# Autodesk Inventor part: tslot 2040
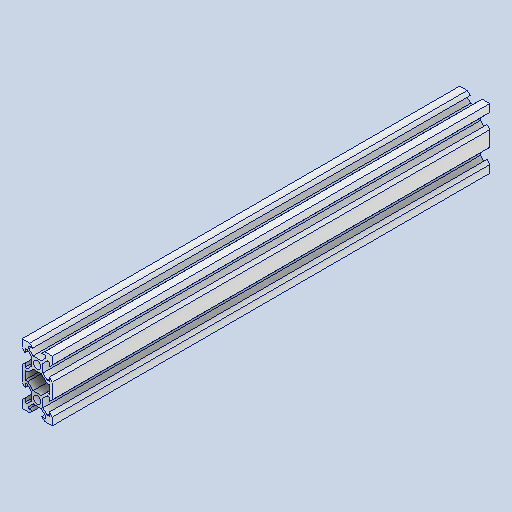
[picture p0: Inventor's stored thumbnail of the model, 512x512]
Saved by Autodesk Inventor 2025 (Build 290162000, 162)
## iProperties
Created: 2024-09
Part Number: tslot 2040
Material: Alluminio 6061
Document SubType Name: Modeling
Designer: Ryzen5700u
Density: 2.7 g/cm^3
Appearance: Default
Author: Ryzen5700u
Revision Number: ANY
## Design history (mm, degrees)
feature "Solido1"
node "Solido2"
